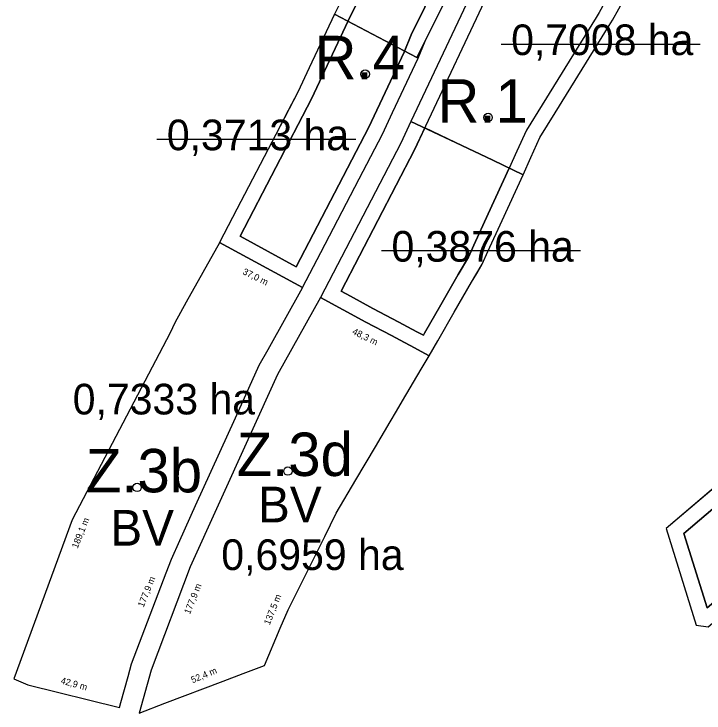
# Model space of a CAD drawing. Extents: x -554894 to -553703, y -1185789 to -1185042.
# Drawn here: x -554894.4 to -554624.2, y -1185485.1 to -1185211.3 of the extents above; entities that cross this region are included whole.
import ezdxf

# ---------------------------------------------------------------- set-up
doc = ezdxf.new("R2010")
doc.units = 0
for name, color, linetype in [('BILA_TECKA', 7, 'Continuous'), ('ID_navrh', 7, 'Continuous'), ('LEG_prac_vykres_ZPF', 7, 'Continuous'), ('navrh_BV', 7, 'Continuous'), ('OBRYS_PLOCH', 7, 'Continuous'), ('REGULATIV_navrh', 7, 'Continuous'), ('rezerva_BV', 7, 'Continuous'), ('upusteno_platny_UP', 7, 'Continuous'), ('upusteno_zmena_1', 7, 'Continuous'), ('vymery', 7, 'Continuous'), ('ZASTAVITELNA_PLOCHA', 7, 'Continuous')]:
    doc.layers.add(name, color=color, linetype=linetype)

msp = doc.modelspace()

# ---------------------------------------------------------------- linework, layer by layer
at = {"layer": 'BILA_TECKA'}
for centre in [(-554756.84, -1185234.83), (-554708.72, -1185251.8), (-554787.09, -1185390.32), (-554846.15, -1185396.73)]:
    msp.add_circle(centre, 1.64, dxfattribs=at)
at = {"layer": 'LEG_prac_vykres_ZPF'}
for p, q in [((-554733.49, -1185255.92), (-554737.54, -1185264.52)), ((-554721.52, -1185261.61), (-554733.49, -1185255.92)), ((-554706.89, -1185268.57), (-554721.52, -1185261.61)), ((-554737.54, -1185264.52), (-554766.29, -1185319.86)), ((-554700.41, -1185271.65), (-554706.89, -1185268.57)), ((-554708.67, -1185289.63), (-554700.45, -1185271.74)), ((-554700.45, -1185271.74), (-554700.41, -1185271.65)), ((-554714.27, -1185301.8), (-554708.67, -1185289.63)), ((-554716.42, -1185306.48), (-554714.27, -1185301.8)), ((-554720.39, -1185313.38), (-554716.42, -1185306.48)), ((-554753.81, -1185326.66), (-554743.71, -1185331.94))]:
    msp.add_line(p, q, dxfattribs=at)
for points in [[(-554741.6, -1185226.21), (-554738.8, -1185219.49), (-554728.14, -1185197.66), (-554722.87, -1185186.48), (-554704.58, -1185138.55), (-554725.82, -1185127.02), (-554747.57, -1185181.64), (-554763.45, -1185213.94), (-554777.88, -1185244.55), (-554805.8, -1185298.3), (-554783.85, -1185310.28), (-554755.47, -1185255.65), (-554741.6, -1185226.21)], [(-554736.41, -1185335.86), (-554734.07, -1185337.13), (-554733.62, -1185336.34), (-554727.18, -1185325.15), (-554720.39, -1185313.38)], [(-554766.29, -1185319.86), (-554762.58, -1185321.88), (-554753.81, -1185326.66)], [(-554513, -1185350.16), (-554532.23, -1185329.76), (-554632.02, -1185414.79), (-554622.99, -1185443.89), (-554513, -1185350.16)], [(-554743.71, -1185331.94), (-554738.6, -1185334.72), (-554736.41, -1185335.86)]]:
    msp.add_lwpolyline(points, dxfattribs=at)
at = {"layer": 'navrh_BV'}
for p, q in [((-554813.94, -1185300.96), (-554826.92, -1185324.2)), ((-554813.94, -1185300.96), (-554826.92, -1185324.2)), ((-554813.94, -1185300.96), (-554826.92, -1185324.2)), ((-554813.83, -1185300.75), (-554813.94, -1185300.96)), ((-554813.83, -1185300.75), (-554813.94, -1185300.96)), ((-554813.83, -1185300.75), (-554813.94, -1185300.96)), ((-554781.34, -1185318.48), (-554813.83, -1185300.75)), ((-554781.34, -1185318.48), (-554813.83, -1185300.75)), ((-554781.34, -1185318.48), (-554813.83, -1185300.75)), ((-554774.32, -1185322.31), (-554791.18, -1185352.5)), ((-554774.32, -1185322.31), (-554791.18, -1185352.5)), ((-554774.32, -1185322.31), (-554791.18, -1185352.5)), ((-554765.45, -1185327.15), (-554774.32, -1185322.31)), ((-554765.45, -1185327.15), (-554774.32, -1185322.31)), ((-554826.92, -1185324.2), (-554831.39, -1185332.2)), ((-554756.64, -1185331.95), (-554765.45, -1185327.15)), ((-554756.64, -1185331.95), (-554765.45, -1185327.15)), ((-554831.39, -1185332.2), (-554833.18, -1185336.15)), ((-554746.53, -1185337.24), (-554756.64, -1185331.95)), ((-554746.53, -1185337.24), (-554756.64, -1185331.95)), ((-554833.18, -1185336.15), (-554871.53, -1185409.38)), ((-554833.18, -1185336.15), (-554871.53, -1185409.38)), ((-554833.18, -1185336.15), (-554871.53, -1185409.38)), ((-554741.42, -1185340.01), (-554746.53, -1185337.24)), ((-554739.23, -1185341.16), (-554741.42, -1185340.01)), ((-554731.79, -1185345.18), (-554739.23, -1185341.16)), ((-554731.79, -1185345.18), (-554739.23, -1185341.16)), ((-554798.33, -1185348.89), (-554794.88, -1185342.72)), ((-554798.33, -1185348.89), (-554794.88, -1185342.72)), ((-554798.33, -1185348.89), (-554794.88, -1185342.72)), ((-554734.88, -1185350.42), (-554731.79, -1185345.18)), ((-554734.88, -1185350.42), (-554731.79, -1185345.18)), ((-554734.88, -1185350.42), (-554731.79, -1185345.18)), ((-554807.68, -1185369.52), (-554798.33, -1185348.89)), ((-554807.68, -1185369.52), (-554798.33, -1185348.89)), ((-554807.68, -1185369.52), (-554798.33, -1185348.89)), ((-554742.18, -1185362.81), (-554734.88, -1185350.42)), ((-554742.18, -1185362.81), (-554734.88, -1185350.42)), ((-554742.18, -1185362.81), (-554734.88, -1185350.42)), ((-554791.18, -1185352.5), (-554825.35, -1185427.87)), ((-554791.18, -1185352.5), (-554825.35, -1185427.87)), ((-554791.18, -1185352.5), (-554825.35, -1185427.87)), ((-554744.55, -1185366.82), (-554742.18, -1185362.81)), ((-554744.55, -1185366.82), (-554742.18, -1185362.81)), ((-554744.55, -1185366.82), (-554742.18, -1185362.81)), ((-554747.05, -1185371.06), (-554744.55, -1185366.82)), ((-554747.05, -1185371.06), (-554744.55, -1185366.82)), ((-554747.05, -1185371.06), (-554744.55, -1185366.82)), ((-554823.22, -1185403.79), (-554807.68, -1185369.52)), ((-554823.22, -1185403.79), (-554807.68, -1185369.52)), ((-554823.22, -1185403.79), (-554807.68, -1185369.52)), ((-554752.81, -1185380.83), (-554747.05, -1185371.06)), ((-554752.81, -1185380.83), (-554747.05, -1185371.06)), ((-554752.81, -1185380.83), (-554747.05, -1185371.06)), ((-554760.45, -1185393.79), (-554752.81, -1185380.83)), ((-554760.45, -1185393.79), (-554752.81, -1185380.83)), ((-554760.45, -1185393.79), (-554752.81, -1185380.83)), ((-554768.14, -1185406.83), (-554760.45, -1185393.79)), ((-554768.14, -1185406.83), (-554760.45, -1185393.79)), ((-554768.14, -1185406.83), (-554760.45, -1185393.79)), ((-554829.45, -1185417.54), (-554823.22, -1185403.79)), ((-554829.45, -1185417.54), (-554823.22, -1185403.79)), ((-554829.45, -1185417.54), (-554823.22, -1185403.79)), ((-554772.69, -1185415.93), (-554768.14, -1185406.83)), ((-554772.69, -1185415.93), (-554768.14, -1185406.83)), ((-554772.69, -1185415.93), (-554768.14, -1185406.83)), ((-554871.53, -1185409.38), (-554894.36, -1185471.66)), ((-554786.97, -1185444.66), (-554772.69, -1185415.93)), ((-554786.97, -1185444.66), (-554772.69, -1185415.93)), ((-554786.97, -1185444.66), (-554772.69, -1185415.93)), ((-554832.74, -1185424.8), (-554829.45, -1185417.54)), ((-554832.74, -1185424.8), (-554829.45, -1185417.54)), ((-554832.74, -1185424.8), (-554829.45, -1185417.54)), ((-554834.79, -1185430.19), (-554832.74, -1185424.8)), ((-554834.79, -1185430.19), (-554832.74, -1185424.8)), ((-554834.79, -1185430.19), (-554832.74, -1185424.8)), ((-554848.3, -1185465.81), (-554834.79, -1185430.19)), ((-554848.3, -1185465.81), (-554834.79, -1185430.19)), ((-554848.3, -1185465.81), (-554834.79, -1185430.19)), ((-554825.35, -1185427.87), (-554840.69, -1185468.29)), ((-554825.35, -1185427.87), (-554840.69, -1185468.29)), ((-554825.35, -1185427.87), (-554840.69, -1185468.29)), ((-554790.07, -1185451.89), (-554786.97, -1185444.66)), ((-554790.07, -1185451.89), (-554786.97, -1185444.66)), ((-554790.07, -1185451.89), (-554786.97, -1185444.66)), ((-554796.32, -1185466.44), (-554790.07, -1185451.89)), ((-554796.32, -1185466.44), (-554790.07, -1185451.89)), ((-554796.32, -1185466.44), (-554790.07, -1185451.89)), ((-554790.07, -1185451.89), (-554790.07, -1185451.89)), ((-554790.07, -1185451.89), (-554790.07, -1185451.89)), ((-554790.07, -1185451.89), (-554790.07, -1185451.89)), ((-554849.67, -1185470.78), (-554848.3, -1185465.81)), ((-554849.67, -1185470.78), (-554848.3, -1185465.81)), ((-554849.67, -1185470.78), (-554848.3, -1185465.81)), ((-554840.69, -1185468.29), (-554845.3, -1185485.1)), ((-554840.69, -1185468.29), (-554845.3, -1185485.1)), ((-554840.69, -1185468.29), (-554845.3, -1185485.1)), ((-554804.61, -1185469.6), (-554796.32, -1185466.44)), ((-554804.61, -1185469.6), (-554796.32, -1185466.44)), ((-554804.61, -1185469.6), (-554796.32, -1185466.44)), ((-554852.46, -1185480.97), (-554849.67, -1185470.78)), ((-554852.46, -1185480.97), (-554849.67, -1185470.78)), ((-554852.46, -1185480.97), (-554849.67, -1185470.78)), ((-554812.49, -1185472.6), (-554804.61, -1185469.6)), ((-554812.49, -1185472.6), (-554804.61, -1185469.6)), ((-554812.49, -1185472.6), (-554804.61, -1185469.6)), ((-554894.36, -1185471.66), (-554888.92, -1185474.12)), ((-554835.3, -1185481.29), (-554812.49, -1185472.6)), ((-554835.3, -1185481.29), (-554812.49, -1185472.6)), ((-554835.3, -1185481.29), (-554812.49, -1185472.6)), ((-554888.92, -1185474.12), (-554853.01, -1185482.98)), ((-554888.92, -1185474.12), (-554853.01, -1185482.98)), ((-554888.92, -1185474.12), (-554853.01, -1185482.98)), ((-554853.01, -1185482.98), (-554852.47, -1185480.98)), ((-554853.01, -1185482.98), (-554852.47, -1185480.98)), ((-554853.01, -1185482.98), (-554852.47, -1185480.98)), ((-554852.47, -1185480.98), (-554852.46, -1185480.97)), ((-554852.47, -1185480.98), (-554852.46, -1185480.97)), ((-554852.47, -1185480.98), (-554852.46, -1185480.97)), ((-554845.3, -1185485.1), (-554835.3, -1185481.29)), ((-554845.3, -1185485.1), (-554835.3, -1185481.29)), ((-554845.3, -1185485.1), (-554835.3, -1185481.29))]:
    msp.add_line(p, q, dxfattribs=at)
for points in [[(-554794.88, -1185342.72), (-554781.36, -1185318.51), (-554781.34, -1185318.48)], [(-554794.88, -1185342.72), (-554781.36, -1185318.51), (-554781.34, -1185318.48)], [(-554794.88, -1185342.72), (-554781.36, -1185318.51), (-554781.34, -1185318.48)], [(-554731.79, -1185345.18), (-554739.23, -1185341.16), (-554741.42, -1185340.01), (-554746.53, -1185337.24), (-554756.64, -1185331.95), (-554765.45, -1185327.15), (-554774.32, -1185322.31)], [(-554826.92, -1185324.2), (-554831.39, -1185332.2), (-554833.18, -1185336.15)], [(-554826.92, -1185324.2), (-554831.39, -1185332.2), (-554833.18, -1185336.15)], [(-554739.23, -1185341.16), (-554741.42, -1185340.01), (-554746.53, -1185337.24)], [(-554871.53, -1185409.38), (-554894.36, -1185471.66), (-554888.92, -1185474.12)], [(-554871.53, -1185409.38), (-554894.36, -1185471.66), (-554888.92, -1185474.12)]]:
    msp.add_lwpolyline(points, dxfattribs=at)
at = {"layer": 'OBRYS_PLOCH'}
for p, q in [((-554813.94, -1185300.96), (-554826.92, -1185324.2)), ((-554813.83, -1185300.75), (-554813.94, -1185300.96)), ((-554781.34, -1185318.48), (-554813.83, -1185300.75)), ((-554794.88, -1185342.72), (-554781.36, -1185318.51)), ((-554781.36, -1185318.51), (-554781.34, -1185318.48)), ((-554774.32, -1185322.31), (-554791.18, -1185352.5)), ((-554765.45, -1185327.15), (-554774.32, -1185322.31)), ((-554756.64, -1185331.95), (-554765.45, -1185327.15)), ((-554833.18, -1185336.15), (-554871.53, -1185409.38)), ((-554739.23, -1185341.16), (-554741.42, -1185340.01)), ((-554731.79, -1185345.18), (-554739.23, -1185341.16)), ((-554798.33, -1185348.89), (-554794.88, -1185342.72)), ((-554734.88, -1185350.42), (-554731.79, -1185345.18)), ((-554807.68, -1185369.52), (-554798.33, -1185348.89)), ((-554742.18, -1185362.81), (-554734.88, -1185350.42)), ((-554791.18, -1185352.5), (-554825.35, -1185427.87)), ((-554744.55, -1185366.82), (-554742.18, -1185362.81)), ((-554747.05, -1185371.06), (-554744.55, -1185366.82)), ((-554823.22, -1185403.79), (-554807.68, -1185369.52)), ((-554752.81, -1185380.83), (-554747.05, -1185371.06)), ((-554760.45, -1185393.79), (-554752.81, -1185380.83)), ((-554768.14, -1185406.83), (-554760.45, -1185393.79)), ((-554829.45, -1185417.54), (-554823.22, -1185403.79)), ((-554772.69, -1185415.93), (-554768.14, -1185406.83)), ((-554786.97, -1185444.66), (-554772.69, -1185415.93)), ((-554832.74, -1185424.8), (-554829.45, -1185417.54)), ((-554834.79, -1185430.19), (-554832.74, -1185424.8)), ((-554848.3, -1185465.81), (-554834.79, -1185430.19)), ((-554825.35, -1185427.87), (-554840.69, -1185468.29)), ((-554790.07, -1185451.89), (-554786.97, -1185444.66)), ((-554796.32, -1185466.44), (-554790.07, -1185451.89)), ((-554790.07, -1185451.89), (-554790.07, -1185451.89)), ((-554849.67, -1185470.78), (-554848.3, -1185465.81)), ((-554840.69, -1185468.29), (-554845.3, -1185485.1)), ((-554804.61, -1185469.6), (-554796.32, -1185466.44)), ((-554852.46, -1185480.97), (-554849.67, -1185470.78)), ((-554812.49, -1185472.6), (-554804.61, -1185469.6)), ((-554835.3, -1185481.29), (-554812.49, -1185472.6)), ((-554888.92, -1185474.12), (-554853.01, -1185482.98)), ((-554853.01, -1185482.98), (-554852.47, -1185480.98)), ((-554852.47, -1185480.98), (-554852.46, -1185480.97)), ((-554845.3, -1185485.1), (-554835.3, -1185481.29))]:
    msp.add_line(p, q, dxfattribs=at)
for points in [[(-554826.92, -1185324.2), (-554831.39, -1185332.2), (-554833.18, -1185336.15)], [(-554741.42, -1185340.01), (-554746.53, -1185337.24), (-554756.64, -1185331.95)], [(-554871.53, -1185409.38), (-554894.36, -1185471.66), (-554888.92, -1185474.12)]]:
    msp.add_lwpolyline(points, dxfattribs=at)
at = {"layer": 'rezerva_BV'}
for p, q in [((-554753.06, -1185179.2), (-554768.86, -1185211.34)), ((-554709.98, -1185191.97), (-554738.91, -1185253.34)), ((-554660.04, -1185213.75), (-554651.54, -1185198.32)), ((-554733.33, -1185221.96), (-554722.73, -1185200.26)), ((-554768.86, -1185211.34), (-554778.8, -1185232.44)), ((-554661.31, -1185215.81), (-554660.04, -1185213.75)), ((-554671.87, -1185232.89), (-554661.31, -1185215.81)), ((-554736.11, -1185228.65), (-554733.33, -1185221.96)), ((-554746.09, -1185249.82), (-554736.11, -1185228.65)), ((-554778.8, -1185232.44), (-554783.25, -1185241.89)), ((-554682.43, -1185249.97), (-554671.87, -1185232.89)), ((-554783.25, -1185241.89), (-554791.87, -1185258.48)), ((-554687.53, -1185246.82), (-554693.73, -1185256.85)), ((-554688.42, -1185259.67), (-554682.43, -1185249.97)), ((-554738.91, -1185253.34), (-554742.92, -1185261.86)), ((-554693.73, -1185256.85), (-554697.42, -1185265.03)), ((-554791.87, -1185258.48), (-554807.06, -1185287.73)), ((-554691.95, -1185267.5), (-554688.42, -1185259.67)), ((-554742.92, -1185261.86), (-554774.32, -1185322.31)), ((-554697.42, -1185265.03), (-554700.45, -1185271.74)), ((-554694.99, -1185274.23), (-554691.95, -1185267.5)), ((-554700.45, -1185271.74), (-554708.67, -1185289.63)), ((-554774.2, -1185304.73), (-554759.23, -1185275.9)), ((-554703.22, -1185292.14), (-554694.99, -1185274.23)), ((-554807.06, -1185287.73), (-554813.83, -1185300.75)), ((-554708.67, -1185289.63), (-554714.27, -1185301.8)), ((-554708.82, -1185304.31), (-554703.22, -1185292.14)), ((-554813.83, -1185300.75), (-554781.34, -1185318.48)), ((-554714.27, -1185301.8), (-554716.42, -1185306.48)), ((-554781.34, -1185318.48), (-554774.2, -1185304.73)), ((-554716.42, -1185306.48), (-554720.39, -1185313.38)), ((-554711.08, -1185309.23), (-554708.82, -1185304.31)), ((-554715.19, -1185316.37), (-554711.08, -1185309.23)), ((-554721.98, -1185328.15), (-554715.19, -1185316.37)), ((-554531.78, -1185321.49), (-554638.92, -1185412.79)), ((-554743.71, -1185331.94), (-554753.81, -1185326.66)), ((-554728.42, -1185339.33), (-554721.98, -1185328.15)), ((-554756.64, -1185331.95), (-554746.53, -1185337.24)), ((-554746.53, -1185337.24), (-554741.42, -1185340.01)), ((-554731.79, -1185345.18), (-554728.42, -1185339.33)), ((-554741.42, -1185340.01), (-554739.23, -1185341.16)), ((-554739.23, -1185341.16), (-554731.79, -1185345.18))]:
    msp.add_line(p, q, dxfattribs=at)
for points in [[(-554755.47, -1185255.65), (-554783.85, -1185310.28), (-554805.8, -1185298.3), (-554777.88, -1185244.55), (-554763.45, -1185213.94), (-554747.57, -1185181.64), (-554725.82, -1185127.02), (-554704.58, -1185138.55), (-554722.87, -1185186.48), (-554728.14, -1185197.66), (-554738.8, -1185219.49), (-554741.6, -1185226.21), (-554755.47, -1185255.65)], [(-554655.3, -1185156.98), (-554639.41, -1185163.85), (-554647.14, -1185177.88), (-554656.8, -1185195.43), (-554665.22, -1185210.73), (-554666.42, -1185212.66), (-554687.53, -1185246.82)], [(-554766.29, -1185319.86), (-554737.54, -1185264.52), (-554704.46, -1185194.32)], [(-554759.23, -1185275.9), (-554750.09, -1185258.31), (-554746.09, -1185249.82)], [(-554720.39, -1185313.38), (-554727.18, -1185325.15), (-554733.62, -1185336.34), (-554734.07, -1185337.13), (-554736.41, -1185335.86)], [(-554753.81, -1185326.66), (-554762.58, -1185321.88), (-554766.29, -1185319.86)], [(-554774.32, -1185322.31), (-554765.45, -1185327.15), (-554756.64, -1185331.95)], [(-554622.99, -1185443.89), (-554632.02, -1185414.79), (-554532.23, -1185329.76), (-554513, -1185350.16), (-554622.99, -1185443.89)], [(-554736.41, -1185335.86), (-554738.6, -1185334.72), (-554743.71, -1185331.94)], [(-554638.92, -1185412.79), (-554627.18, -1185450.64), (-554622.56, -1185451.39)]]:
    msp.add_lwpolyline(points, dxfattribs=at)
at = {"layer": 'upusteno_platny_UP'}
for p, q in [((-554733.33, -1185221.96), (-554722.73, -1185200.26)), ((-554769.05, -1185211.23), (-554768.86, -1185211.34)), ((-554768.86, -1185211.34), (-554736.6, -1185228.38)), ((-554736.6, -1185228.38), (-554733.33, -1185221.96))]:
    msp.add_line(p, q, dxfattribs=at)
for points in [[(-554531.78, -1185321.49), (-554556.23, -1185342.33), (-554638.92, -1185412.79)], [(-554638.92, -1185412.79), (-554627.18, -1185450.64), (-554622.56, -1185451.39), (-554504.31, -1185350.64)]]:
    msp.add_lwpolyline(points, dxfattribs=at)
at = {"layer": 'upusteno_zmena_1'}
for p, q in [((-554709.98, -1185191.97), (-554738.91, -1185253.34)), ((-554660.04, -1185213.75), (-554651.54, -1185198.32)), ((-554768.86, -1185211.34), (-554778.8, -1185232.44)), ((-554736.6, -1185228.38), (-554768.86, -1185211.34)), ((-554671.87, -1185232.89), (-554661.31, -1185215.81)), ((-554746.09, -1185249.82), (-554736.11, -1185228.65)), ((-554736.11, -1185228.65), (-554736.6, -1185228.38)), ((-554778.8, -1185232.44), (-554783.25, -1185241.89)), ((-554682.43, -1185249.97), (-554671.87, -1185232.89)), ((-554688.42, -1185259.67), (-554682.43, -1185249.97)), ((-554738.91, -1185253.34), (-554742.92, -1185261.86)), ((-554738.91, -1185253.34), (-554721.52, -1185261.61)), ((-554721.52, -1185261.61), (-554738.91, -1185253.34)), ((-554791.87, -1185258.48), (-554807.06, -1185287.73)), ((-554691.95, -1185267.5), (-554688.42, -1185259.67)), ((-554742.92, -1185261.86), (-554774.32, -1185322.31)), ((-554721.52, -1185261.61), (-554706.89, -1185268.57)), ((-554706.89, -1185268.57), (-554721.52, -1185261.61)), ((-554706.89, -1185268.57), (-554694.99, -1185274.23)), ((-554694.99, -1185274.23), (-554706.89, -1185268.57)), ((-554694.99, -1185274.23), (-554691.95, -1185267.5)), ((-554774.2, -1185304.73), (-554759.23, -1185275.9)), ((-554703.22, -1185292.14), (-554694.99, -1185274.23)), ((-554807.06, -1185287.73), (-554813.83, -1185300.75)), ((-554708.82, -1185304.31), (-554703.22, -1185292.14)), ((-554813.83, -1185300.75), (-554781.34, -1185318.48)), ((-554781.34, -1185318.48), (-554774.2, -1185304.73)), ((-554728.42, -1185339.33), (-554721.98, -1185328.15)), ((-554756.64, -1185331.95), (-554746.53, -1185337.24)), ((-554746.53, -1185337.24), (-554741.42, -1185340.01)), ((-554731.79, -1185345.18), (-554728.42, -1185339.33)), ((-554741.42, -1185340.01), (-554739.23, -1185341.16)), ((-554739.23, -1185341.16), (-554731.79, -1185345.18))]:
    msp.add_line(p, q, dxfattribs=at)
for points in [[(-554661.31, -1185215.81), (-554660.04, -1185213.75), (-554660.04, -1185213.75)], [(-554783.25, -1185241.89), (-554787.02, -1185249.14), (-554791.87, -1185258.48)], [(-554759.23, -1185275.9), (-554750.09, -1185258.31), (-554746.09, -1185249.82)], [(-554721.98, -1185328.15), (-554715.19, -1185316.37), (-554713.18, -1185312.89), (-554711.08, -1185309.23), (-554708.82, -1185304.31)], [(-554774.32, -1185322.31), (-554765.45, -1185327.15), (-554756.64, -1185331.95)]]:
    msp.add_lwpolyline(points, dxfattribs=at)
at = {"layer": 'vymery'}
for points in [[(-554703.61, -1185223.05), (-554703.61, -1185223.05), (-554625.62, -1185223.05)], [(-554838.45, -1185260.32), (-554838.45, -1185260.32), (-554760.46, -1185260.32)], [(-554750.47, -1185303.96), (-554750.47, -1185303.96), (-554672.48, -1185303.96)]]:
    msp.add_lwpolyline(points, dxfattribs=at)
at = {"layer": 'ZASTAVITELNA_PLOCHA'}
for p, q in [((-554813.94, -1185300.96), (-554826.92, -1185324.2)), ((-554813.83, -1185300.75), (-554813.94, -1185300.96)), ((-554781.34, -1185318.48), (-554813.83, -1185300.75)), ((-554774.32, -1185322.31), (-554791.18, -1185352.5)), ((-554826.92, -1185324.2), (-554831.39, -1185332.2)), ((-554831.39, -1185332.2), (-554833.18, -1185336.15)), ((-554746.53, -1185337.24), (-554756.64, -1185331.95)), ((-554833.18, -1185336.15), (-554871.53, -1185409.38)), ((-554731.79, -1185345.18), (-554739.23, -1185341.16)), ((-554798.33, -1185348.89), (-554794.88, -1185342.72)), ((-554734.88, -1185350.42), (-554731.79, -1185345.18)), ((-554807.68, -1185369.52), (-554798.33, -1185348.89)), ((-554742.18, -1185362.81), (-554734.88, -1185350.42)), ((-554791.18, -1185352.5), (-554825.35, -1185427.87)), ((-554744.55, -1185366.82), (-554742.18, -1185362.81)), ((-554747.05, -1185371.06), (-554744.55, -1185366.82)), ((-554823.22, -1185403.79), (-554807.68, -1185369.52)), ((-554752.81, -1185380.83), (-554747.05, -1185371.06)), ((-554760.45, -1185393.79), (-554752.81, -1185380.83)), ((-554768.14, -1185406.83), (-554760.45, -1185393.79)), ((-554829.45, -1185417.54), (-554823.22, -1185403.79)), ((-554772.69, -1185415.93), (-554768.14, -1185406.83)), ((-554871.53, -1185409.38), (-554894.36, -1185471.66)), ((-554786.97, -1185444.66), (-554772.69, -1185415.93)), ((-554832.74, -1185424.8), (-554829.45, -1185417.54)), ((-554834.79, -1185430.19), (-554832.74, -1185424.8)), ((-554848.3, -1185465.81), (-554834.79, -1185430.19)), ((-554825.35, -1185427.87), (-554840.69, -1185468.29)), ((-554790.07, -1185451.89), (-554786.97, -1185444.66)), ((-554796.32, -1185466.44), (-554790.07, -1185451.89)), ((-554790.07, -1185451.89), (-554790.07, -1185451.89)), ((-554849.67, -1185470.78), (-554848.3, -1185465.81)), ((-554840.69, -1185468.29), (-554845.3, -1185485.1)), ((-554804.61, -1185469.6), (-554796.32, -1185466.44)), ((-554852.46, -1185480.97), (-554849.67, -1185470.78)), ((-554812.49, -1185472.6), (-554804.61, -1185469.6)), ((-554894.36, -1185471.66), (-554888.92, -1185474.12)), ((-554835.3, -1185481.29), (-554812.49, -1185472.6)), ((-554888.92, -1185474.12), (-554853.01, -1185482.98)), ((-554853.01, -1185482.98), (-554852.47, -1185480.98)), ((-554852.47, -1185480.98), (-554852.46, -1185480.97)), ((-554845.3, -1185485.1), (-554835.3, -1185481.29))]:
    msp.add_line(p, q, dxfattribs=at)
for points in [[(-554794.88, -1185342.72), (-554781.36, -1185318.51), (-554781.34, -1185318.48)], [(-554756.64, -1185331.95), (-554765.45, -1185327.15), (-554774.32, -1185322.31)], [(-554739.23, -1185341.16), (-554741.42, -1185340.01), (-554746.53, -1185337.24)]]:
    msp.add_lwpolyline(points, dxfattribs=at)

# ---------------------------------------------------------------- texts
at = {"layer": 'ID_navrh'}
for s, p in [('R.4', (-554776.66, -1185236.84)), ('R.1', (-554728.55, -1185253.82)), ('Z.3d', (-554807.15, -1185392.26)), ('Z.3b', (-554866.2, -1185398.66))]:
    msp.add_text(s, height=17, dxfattribs=at).set_placement(p)
at = {"layer": 'REGULATIV_navrh'}
for p in [(-554798.84, -1185410.43), (-554856.66, -1185419.55)]:
    msp.add_text('BV', height=14, dxfattribs=at).set_placement(p)
at = {"layer": 'vymery'}
for s, p in [('0,7008 ha', (-554699.69, -1185227.39)), ('0,3713 ha', (-554834.52, -1185264.66)), ('0,3876 ha', (-554746.55, -1185308.3)), ('0,7333 ha', (-554871.36, -1185368.14)), ('0,6959 ha', (-554813.18, -1185429.08))]:
    msp.add_text(s, height=12, dxfattribs=at).set_placement(p)
for s, rotation, p in [('37,0 m', 333.8757, (-554805.1, -1185313.05)), ('48,3 m', 333.8757, (-554762.16, -1185336.51)), ('189,1 m', 68.1532, (-554869.46, -1185420.85)), ('177,9 m', 68.1532, (-554843.61, -1185443.89)), ('177,9 m', 68.1532, (-554825.48, -1185446.64)), ('137,5 m', 68.1532, (-554794.25, -1185450.83)), ('52,4 m', 22.6892, (-554824.4, -1185473.49)), ('42,9 m', 344.5628, (-554876.26, -1185473.49))]:
    msp.add_text(s, height=2.592, rotation=rotation, dxfattribs=at).set_placement(p)

doc.saveas('drawing.dxf')
